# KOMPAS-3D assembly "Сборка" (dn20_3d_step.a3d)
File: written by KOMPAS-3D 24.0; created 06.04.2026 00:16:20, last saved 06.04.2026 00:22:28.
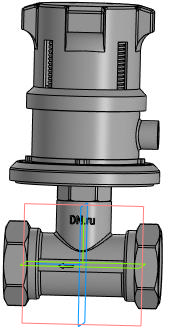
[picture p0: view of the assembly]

Document properties: Автор: tyuri; Полное имя файла: D:\Аутсорс\VBA0000E-T Клапан балансировочный автоматический DN.ru\DN20\Исходные файлы\dn20_3d_step.a3d

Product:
- Component [detail]: Деталь  | qty 1  | Автор: tyuri; additional columns: Типовые; source file: Деталь - Деталь.m3d
- Component [detail]: Деталь  | designation Деталь_1  | qty 1  | Автор: tyuri; additional columns: Типовые; source file: Деталь_1 - Деталь.m3d
- Component [detail]: Деталь  | qty 1  | Автор: tyuri; additional columns: Типовые; source file: Деталь_3 - Деталь.m3d
- Part/product: Сборка
    Масса: 1.11353

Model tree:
1. Эскиз:1
2. Эскиз:3  (labels: Грань.Твердое тело1)
3. Элемент выдавливания:2
     Расстояние 2 = 10
4. Элемент вращения:1  (labels: Грань.Твердое тело1)
     Угол 1 = 360
5. Смещенная плоскость:1
     Расстояние = -13
6. Эскиз:4
7. Элемент выдавливания:3
     Расстояние 2 = 44.5
8. Смещенная плоскость:2
     Расстояние = 13
9. Эскиз:5
10. Элемент выдавливания:4
     Расстояние 2 = 44.5
11. Эскиз:6  (with: Грань.Элемент выдавливания:3)
12. Элемент вращения:2  (with: Грань.Элемент выдавливания:3)
     Угол 1 = 360
13. Эскиз:7  (with: Грань.Элемент выдавливания:3)
14. Элемент выдавливания:5  (with: Грань.Элемент вращения:1, Грань.Элемент выдавливания:1)  (labels: Грань.Твердое тело1; Твердое тело1)
     Расстояние 1 = 0.001

Referenced files in D:\Аутсорс\VBA0000E-T Клапан балансировочный автоматический DN.ru\DN20\Исходные файлы\: Деталь - Деталь.m3d, Деталь_1 - Деталь.m3d, Деталь_3 - Деталь.m3d
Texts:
  ЛС59
  DN20      PN16
  Деталь_1 Деталь
  Ось Z.Начало координат
  Ось Y.Начало координат
  Плоскость ZY.Начало координат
